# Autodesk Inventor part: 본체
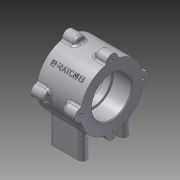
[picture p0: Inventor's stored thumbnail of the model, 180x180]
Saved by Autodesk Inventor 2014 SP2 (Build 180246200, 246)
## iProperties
Created: 2015-03
Part Number: 본체
Material: 알루미늄 6061
Document SubType Name: Modeling
Designer: 201-06
Mass: 450.777 g
Surface Area: 332.694 cm^2
Volume: 166.338 cm^3
Density: 2.71 g/cm^3
Appearance: 알루미늄 - 평지
Author: 201-06
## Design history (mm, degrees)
sketch "스케치1"
  geometry: C1 r 37 at (0, 0); 1 further point
  constraints: 1 centre point, 1 coincident
  dimensions: "d0" = 74 diameter of C1
extrude "돌출1" new body sketch "스케치1" distance "d1" = 52; taper "d2" = 0 deg
sketch "스케치2"
  geometry: L1 (-37, -7)-(-36.332, -7); L2 (-37, 7)-(-36.332, 7); A1 r 37 centre (0, 0) between (-37, 0) and (-36.332, -7) reference; A2 r 7 centre (-37, 0) between (-37, 7) and (-37, -7); 1 further point
  constraints: 5 point on circle, 4 end point, 2 horizontal alignment, 2 tangent, 1 centre point, 1 horizontal, 1 parallel, 1 other
  dimensions: "d3" = 14 diameter of A2
extrude "돌출2" join sketch "스케치2" distance "d5" = 15; taper "d6" = 0 deg
fillet "모깎기1" dims "d7" = 3
fillet "모깎기2" dims "d8" = 3
node "작업 평면1"
sketch "스케치4"
  geometry: L1 (19, -56)-(29, -56); L2 (19, -56)-(19, -20.462); L3 (19, -20.462)-(29, -14.665); L4 (29, -14.665)-(29, -56); 1 further point
  constraints: 8 end point, 1 horizontal, 1 parallel, 1 perpendicular
  dimensions: "d20" = 10 distance of L1.start L1.end; "d21" = 56 distance from line of L1 point (0, 0); "d22" = 19 horizontal distance of L1.start point (0, 0); "d23" = 59.8977 deg angle of L3 L4; "d24" = 27.23161 distance from line of point (0, 0) L3
extrude "돌출3" join sketch "스케치4" stored distance "d25" = 40; taper "d26" = 0 deg
fillet "모깎기3" dims "d27" = 5
fillet "모깎기4" dims "d28" = 3
node "작업 평면5"
sketch "스케치5"
  geometry: L1 (0, -48)-(30, -48) reference; L2 (30, -58)-(0, -58) reference; A1 r 5 centre (30, -5) between (30, -10) and (30, 0) reference; A2 r 5 centre (0, -5) between (0, 0) and (0, -10) reference; A3 r 5 centre (30, -53) between (30, -58) and (30, -48) reference; A4 r 5 centre (0, -53) between (0, -48) and (0, -58) reference; 5 further points
  constraints: 4 coincident
hole "구멍1" sketch "스케치5" at (0, -5), (30, -5), (30, -53), (0, -53) diameter "d30" = 4.134; stored, may be unused: countersink angle "d34" = 90 deg, drill point angle "d36" = 118 deg; dims "d31" = 6, "d32" = 4, "d33" = 2, "d35" = 8
sketch "스케치6"
  geometry: C1 r 23.5 at (0, 0); A1 r 37 centre (0, 0) between (-9.104, 35.863) and (-35.863, 9.104) reference
  constraints: 1 centre point, 1 coincident
  dimensions: "d37" = 47 diameter of C1
extrude "돌출4" cut sketch "스케치6" distance "d38" = 22; taper "d39" = 0 deg
sketch "스케치7"
  geometry: C1 r 23.5 at (0, 0); A1 r 37 centre (0, 0) between (9.104, -35.863) and (35.863, -9.104) reference
  constraints: 1 centre point, 1 coincident
  dimensions: "d40" = 47 diameter of C1
extrude "돌출5" cut sketch "스케치7" distance "d41" = 22; taper "d42" = 0 deg
sketch "스케치8"
  geometry: C1 r 23.5 at (0, 0) reference; C2 r 21 at (0, 0)
  constraints: 1 centre point, 1 coincident
  dimensions: "d43" = 42 diameter of C2
extrude "돌출6" cut sketch "스케치8" stored distance "d44" = 22; taper "d45" = 0 deg
sketch "스케치9"
  geometry: A1 r 7 centre (0, -37) between (-6.889, -38.239) and (6.889, -38.239) reference; A2 r 7 centre (37, 0) between (38.239, -6.889) and (38.239, 6.889) reference; A3 r 7 centre (0, 37) between (6.889, 38.239) and (-6.889, 38.239) reference; A4 r 7 centre (-37, 0) between (-38.239, 6.889) and (-38.239, -6.889) reference; 4 further points
  constraints: 4 coincident
hole "구멍2" sketch "스케치9" at (-37, 0), (0, -37), (37, 0), (0, 37) diameter "d46" = 3.242; stored, may be unused: countersink angle "d50" = 90 deg, drill point angle "d52" = 118 deg; dims "d47" = 8, "d48" = 4, "d49" = 2, "d51" = 11
sketch "스케치10"
  geometry: C1 r 1.621 at (-37, 0) reference; A1 r 7 centre (0, 37) between (6.889, 38.239) and (-6.889, 38.239) reference; A2 r 7 centre (0, -37) between (-6.889, -38.239) and (6.889, -38.239) reference; A3 r 7 centre (37, 0) between (38.239, -6.889) and (38.239, 6.889) reference; 4 further points
  constraints: 4 coincident
hole "구멍3" sketch "스케치10" at (-37, 0), (0, 37), (37, 0), (0, -37) diameter "d53" = 3.242; stored, may be unused: countersink angle "d57" = 90 deg, drill point angle "d59" = 118 deg; dims "d54" = 8, "d55" = 4, "d56" = 2, "d58" = 11
node "작업 평면7"
  node "작업 평면6"
sketch "스케치11"
  geometry: L1 (0, 3.246)-(0, 41.089) reference; 2 further points
  constraints: 1 horizontal alignment, 1 other
  dimensions: "d62" = 26 distance from line of L1 point (-26, 22.168)
feature "엠보싱1" sketch "스케치11" dims "d63" = 0.5, "d64" = 0
chamfer "모따기1" distance "d65" = 1; stored, may be unused: second distance "d66" = 2, angle "d67" = 45 deg
fillet "모깎기5" dims "d68" = 0.3
node "솔리드1"
pattern_circular "원형 패턴1" dims "d10" = 360 deg
mirror "대칭1"
mirror "대칭2"
node "투영된 루프2"
other parameters: "d12" = 26, "d29" = 0, "d60" = 45 deg, "d61" = 56.75
